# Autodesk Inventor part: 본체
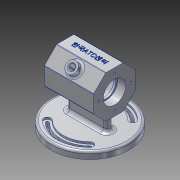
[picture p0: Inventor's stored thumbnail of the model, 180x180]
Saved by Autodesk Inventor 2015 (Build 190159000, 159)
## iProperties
Created: 2017-06
Part Number: 본체
Material: 알루미늄 6061
Document SubType Name: Modeling
Designer: user
Density: 2.7 g/cm^3
Appearance: 알루미늄 - 평지
Mass: 560.726 g
Surface Area: 566.707 cm^2
Volume: 207.676 cm^3
Author: user
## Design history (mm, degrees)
sketch "스케치1"
  geometry: C1 r 55 at (0, 0); 1 further point
  constraints: 1 centre point, 1 coincident
  dimensions: "d0" = 110 diameter of C1
extrude "돌출1" new body sketch "스케치1" distance "d1" = 10; taper "d2" = 0 deg
sketch "스케치2"
  geometry: L1 (0, 0)-(-30.406, 30.406); L2 (0, 0)-(43, 0); L3 (0, 0)-(30.406, 30.406); A1 r 43 centre (0, 0) between (30.406, 30.406) and (-30.406, 30.406); A2 r 48 centre (0, 0) between (33.941, 33.941) and (-33.941, 33.941); A3 r 38 centre (0, 0) between (26.87, 26.87) and (-26.87, 26.87); A4 r 5 centre (30.406, 30.406) between (26.87, 26.87) and (33.941, 33.941); A5 r 5 centre (-30.406, 30.406) between (-33.941, 33.941) and (-26.87, 26.87); A6 r 43 centre (0, 0) between (-30.406, -30.406) and (30.406, -30.406); A7 r 48 centre (0, 0) between (-33.941, -33.941) and (33.941, -33.941); A8 r 38 centre (0, 0) between (-26.87, -26.87) and (26.87, -26.87); A9 r 5 centre (30.406, -30.406) between (33.941, -33.941) and (26.87, -26.87); A10 r 5 centre (-30.406, -30.406) between (-26.87, -26.87) and (-33.941, -33.941); 1 further point
  constraints: 20 point on circle, 10 centre point, 6 end point, 6 symmetric about line, 4 tangent, 1 coincident, 1 equal length, 1 horizontal, 5 other
  dimensions: "d4" = 135 deg angle of L2 L1; "d5" = 90 deg angle of L3 L1; "d6" = 48 radius of A2; "d7" = 38 radius of A3
extrude "돌출2" cut sketch "스케치2" distance "d8" = 3; taper "d9" = 0 deg
sketch "스케치3"
  geometry: L1 (0, 0)-(-30.406, 30.406); L2 (0, 0)-(43, 0); L3 (0, 0)-(30.406, 30.406); A1 r 43 centre (0, 0) between (30.406, 30.406) and (-30.406, 30.406); A2 r 45 centre (0, 0) between (31.82, 31.82) and (-31.82, 31.82); A3 r 41 centre (0, 0) between (28.991, 28.991) and (-28.991, 28.991); A4 r 2 centre (30.406, 30.406) between (28.991, 28.991) and (31.82, 31.82); A5 r 2 centre (-30.406, 30.406) between (-31.82, 31.82) and (-28.991, 28.991); A6 r 43 centre (0, 0) between (-30.406, -30.406) and (30.406, -30.406); A7 r 45 centre (0, 0) between (-31.82, -31.82) and (31.82, -31.82); A8 r 41 centre (0, 0) between (-28.991, -28.991) and (28.991, -28.991); A9 r 2 centre (30.406, -30.406) between (31.82, -31.82) and (28.991, -28.991); A10 r 2 centre (-30.406, -30.406) between (-28.991, -28.991) and (-31.82, -31.82); 1 further point
  constraints: 20 point on circle, 10 centre point, 6 end point, 6 symmetric about line, 4 tangent, 1 coincident, 1 equal length, 1 horizontal, 5 other
  dimensions: "d10" = 135 deg angle of L2 L1; "d11" = 90 deg angle of L3 L1; "d12" = 4 diameter of A4; "d13" = 43 radius of A1
extrude "돌출3" cut sketch "스케치3" stored distance "d14" = 3; taper "d15" = 0 deg
sketch "스케치4"
  geometry: L1 (-24, 0)-(24, 0); L2 (-24, -5)-(24, -5); L3 (24, 5)-(-24, 5); A1 r 5 centre (-24, 0) between (-24, 5) and (-24, -5); A2 r 5 centre (24, 0) between (24, -5) and (24, 5); 1 further point
  constraints: 8 end point, 4 point on circle, 4 tangent, 2 centre point, 1 horizontal, 1 midpoint, 1 parallel
  dimensions: "d16" = 24 distance of point (0, 0) L1.end; "d17" = 10 diameter of A2
extrude "돌출4" join sketch "스케치4" distance "d18" = 30; taper "d19" = 0 deg
sketch "스케치5"
  geometry: L1 (-30, 49.574)-(-30, 74.426); L2 (-30, 74.426)-(-12.426, 92); L3 (-12.426, 92)-(12.426, 92); L4 (12.426, 92)-(30, 74.426); L5 (30, 74.426)-(30, 49.574); L6 (30, 49.574)-(12.426, 32); L7 (12.426, 32)-(-12.426, 32); L8 (-12.426, 32)-(-30, 49.574); L9 (0, 0)-(0, 62); L10 (0, 92)-(0, 62); 1 further point
  constraints: 20 end point, 2 vertical, 1 coincident, 1 midpoint, 17 other
  dimensions: "d20" = 62 distance of L9.start L9.end; "d21" = 60 distance between parallel lines of L1 L5
extrude "돌출5" join sketch "스케치5" stored distance "d22" = 70; taper "d23" = 0 deg
sketch "스케치6"
  geometry: L1 (74.426, -30)-(49.574, -30) reference; L2 (62, -30)-(62, 36.466); L3 (92, 12.426)-(92, -12.426) reference; L4 (92, 0)-(-12.409, 0); C1 r 16 at (62, 0); 1 further point
  constraints: 4 end point, 2 midpoint, 2 point on line, 1 centre point, 1 horizontal, 1 vertical
  dimensions: "d24" = 32 diameter of C1
extrude "돌출6" cut sketch "스케치6" distance "d25" = 12; taper "d26" = 0 deg
sketch "스케치7"
  geometry: C1 r 14 at (0, 0); C2 r 16 at (0, 0) reference; 1 further point
  constraints: 1 centre point, 1 concentric
  dimensions: "d27" = 28 diameter of C1
extrude "돌출7" cut sketch "스케치7" distance "d28" = 3; taper "d29" = 0 deg
sketch "스케치8"
  geometry: C1 r 25 at (0, 0); C2 r 16 at (0, 0) reference; 1 further point
  constraints: 1 centre point, 1 concentric
  dimensions: "d30" = 50 diameter of C1
extrude "돌출8" cut sketch "스케치8" distance "d31" = 40; taper "d32" = 0 deg
sketch "스케치9"
  geometry: C1 r 16 at (-62, 0); C2 r 14 at (-62, 0) reference; 1 further point
  constraints: 1 centre point, 1 concentric
  dimensions: "d33" = 32 diameter of C1
extrude "돌출9" cut sketch "스케치9" distance "d34" = 12; taper "d35" = 0 deg
sketch "스케치10"
  geometry: C1 r 14 at (0, 0); C2 r 16 at (0, 0) reference; 1 further point
  constraints: 1 centre point, 1 concentric
  dimensions: "d36" = 28 diameter of C1
extrude "돌출10" cut sketch "스케치10" distance "d37" = 3; taper "d38" = 0 deg
sketch "스케치11"
  geometry: L1 (0, 0)-(0, 24.853) reference; L2 (0, 12.426)-(115.197, 12.426); C1 r 8 at (35, 12.426); 1 further point
  constraints: 2 end point, 1 centre point, 1 horizontal, 1 midpoint, 1 point on line
  dimensions: "d39" = 16 diameter of C1; "d40" = 35 distance from line of L1 C1.centre
extrude "돌출11" join sketch "스케치11" distance "d41" = 7; taper "d42" = 0 deg
sketch "스케치12"
  geometry: C1 r 4 at (0, 0); C2 r 8 at (0, 0) reference; 1 further point
  constraints: 1 centre point, 1 concentric
  dimensions: "d43" = 8 diameter of C1
extrude "돌출12" cut sketch "스케치12" distance "d44" = 15; taper "d45" = 0 deg
node "작업 평면1"
sketch "스케치13"
  geometry: L1 (0, 24.853)-(0, 42.426) reference; L2 (70, 42.426)-(0, 42.426) reference; 2 further points
  constraints: 1 other
  dimensions: "d47" = 35 distance from line of L1 point (35, 12.426); "d48" = 30 distance from line of L2 point (35, 12.426)
feature "엠보싱1" sketch "스케치13" dims "d1" = 10, "d2" = 0, "d49" = 0.5, "d50" = 0
sketch "스케치14" dims "d51" = 46
  geometry: L1 (62, 0)-(62, -100.505); C1 r 14 at (62, 0) reference; 6 further points
  constraints: 2 end point, 1 point on line, 1 vertical, 1 vertical alignment, 8 other
  dimensions: "d54" = 360 deg dimension on point (62, 0) point (62, -23) (derived)
hole "구멍1" sketch "스케치14" at (62, -23), (85, 0), (62, 23), (39, 0) diameter "d56" = 3.242; stored, may be unused: countersink angle "d60" = 90 deg, drill point angle "d62" = 118 deg; dims "d57" = 8, "d58" = 4, "d59" = 2, "d61" = 10
fillet "모깎기1" dims "d63" = 3
fillet "모깎기2" dims "d64" = 0.3
chamfer "모따기1" distance "d65" = 1; stored, may be unused: second distance "d66" = 2, angle "d67" = 45 deg
fillet "모깎기3" dims "d68" = 5
fillet "모깎기4" dims "d69" = 1
sketch "스케치15" dims "d70" = 46
  geometry: L1 (-62, 0)-(-62, 41.755); C1 r 16 at (-62, 0) reference; 6 further points
  constraints: 2 end point, 1 point on line, 1 vertical, 1 vertical alignment, 8 other
  dimensions: "d73" = 360 deg dimension on point (-62, 0) point (-62, 23) (derived)
hole "구멍2" sketch "스케치15" at (-62, 23), (-85, 0), (-62, -23), (-39, 0) diameter "d75" = 3.242; stored, may be unused: countersink angle "d79" = 90 deg, drill point angle "d81" = 118 deg; dims "d76" = 8, "d77" = 4, "d78" = 2, "d80" = 10
node "솔리드1"
